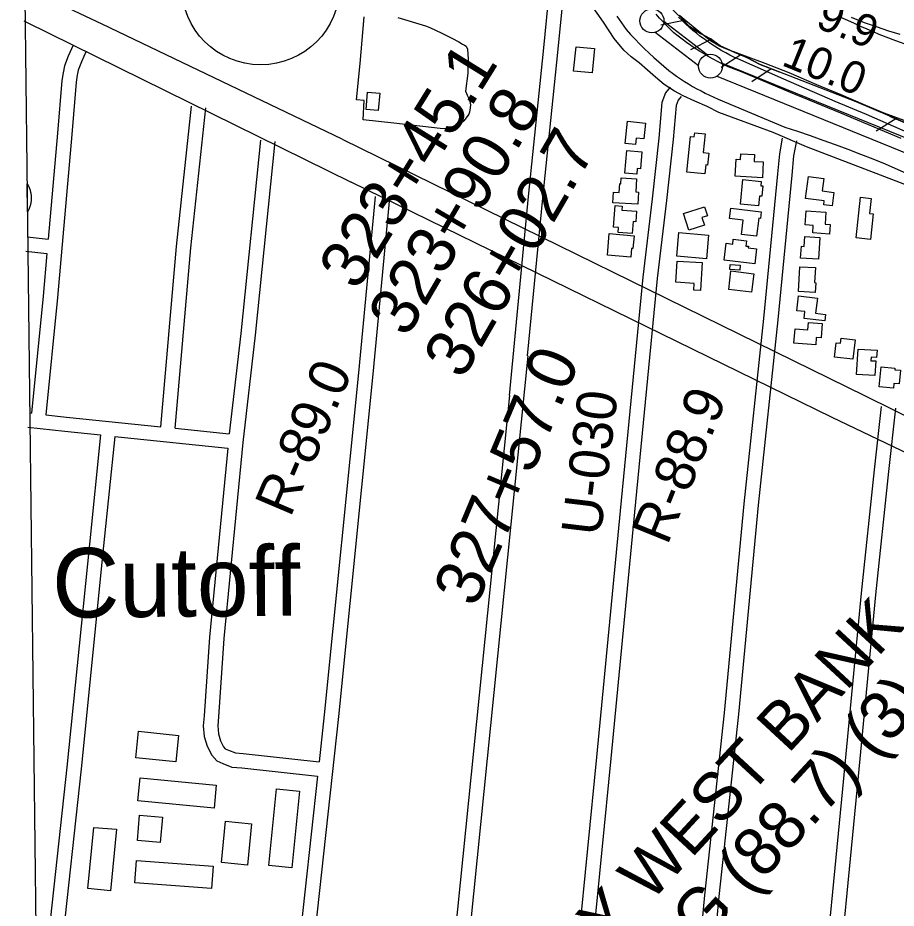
# Model space of a CAD drawing. Extents: x 3704301 to 3742427, y 506229 to 532009.
# Drawn here: x 3708455 to 3710287, y 518201 to 520058 of the extents above; entities that cross this region are included whole.
import ezdxf

# ---------------------------------------------------------------- set-up
doc = ezdxf.new("R2010")
doc.units = 0
for name, color, linetype in [('V-BLDG-OTLN', 7, 'Continuous'), ('V-CHAN-NAID', 7, 'Continuous'), ('V-DOMW-TANK', 7, 'Continuous'), ('V-FLOD-BASE', 7, 'Continuous'), ('V-GRID-FRAM', 7, 'Continuous'), ('V-LEVE-TOET', 7, 'Continuous'), ('V-RIVR-RANG', 7, 'Continuous'), ('V-RIVR-RANG-IDEN', 7, 'Continuous'), ('V-ROAD-CNTR', 7, 'Continuous'), ('V-ROAD-IDEN', 7, 'Continuous'), ('V-RRAP-FSHR', 7, 'Continuous'), ('V-SITE-OTLN', 7, 'Continuous'), ('V-SITE-VEGE', 7, 'Continuous'), ('V-SURV-IDEN', 7, 'Continuous'), ('V-SURV-LINE', 7, 'Continuous'), ('V-TOPO-GNAM-IDEN', 7, 'Continuous'), ('V-TOPO-SHOR', 7, 'Continuous')]:
    doc.layers.add(name, color=color, linetype=linetype)

msp = doc.modelspace()

# ---------------------------------------------------------------- linework, layer by layer
at = {"layer": 'V-BLDG-OTLN'}
for points in [[(3709657.9, 519994.1), (3709652.9, 519943.4), (3709614.4, 519947.3), (3709619.5, 519997.9)], [(3709210.2, 519901.3), (3709207.1, 519864.9), (3709181.6, 519867), (3709184.7, 519903.4)], [(3709743.8, 519793.8), (3709721.7, 519796.1), (3709726.5, 519842.5), (3709764.1, 519838.6), (3709760.7, 519805.7), (3709745.2, 519807.3)], [(3709888.3, 519732.5), (3709850.3, 519736.3), (3709857.9, 519810.7), (3709866.2, 519809.9), (3709867.1, 519818.6), (3709889, 519816.4), (3709885, 519777.3), (3709896.6, 519776.1), (3709894, 519751.1), (3709890.2, 519751.5)], [(3709721.4, 519734.4), (3709725.3, 519781.5), (3709756.6, 519778.9), (3709753.7, 519743.3), (3709746.9, 519743.9), (3709746, 519732.4)], [(3710008.1, 519724.4), (3709951.2, 519727.9), (3709953.3, 519763.2), (3709962.8, 519762.7), (3709963.5, 519774.6), (3709991.5, 519772.9), (3709990.7, 519758.8), (3710010.1, 519757.6)], [(3709744.1, 519695), (3709749.7, 519694.6), (3709748.3, 519669.6), (3709696.5, 519672.4), (3709697.8, 519694.5), (3709709.5, 519693.9), (3709710.5, 519712.4), (3709712.9, 519712.2), (3709713.5, 519724.4), (3709745.6, 519722.6)], [(3710000.3, 519665.9), (3709962.4, 519669.5), (3709967.2, 519720.7), (3710005.7, 519717.1), (3710004.8, 519708), (3710009, 519707.6), (3710007, 519686), (3710002.3, 519686.5)], [(3710098.4, 519681.6), (3710104.6, 519727.1), (3710136.5, 519722.7), (3710133, 519697.1), (3710157.5, 519693.8), (3710153.7, 519666), (3710136, 519668.4), (3710137, 519676.3)], [(3710233.8, 519596.1), (3710204.1, 519599.2), (3710213, 519683.9), (3710234.8, 519681.6), (3710231.5, 519650.3), (3710239.4, 519649.5)], [(3709738.7, 519633.3), (3709736.8, 519608.3), (3709707.2, 519610.6), (3709708, 519620.8), (3709697.4, 519621.6), (3709700.8, 519666.4), (3709715.9, 519665.2), (3709715.3, 519657.3), (3709745.6, 519654.9), (3709743.9, 519632.9)], [(3709843.8, 519650.1), (3709887.7, 519663.7), (3709893.4, 519645.1), (3709882.1, 519641.6), (3709887.1, 519625.4), (3709854.6, 519615.3)], [(3709968, 519636.2), (3709939.9, 519639.7), (3709942.6, 519661.1), (3710005.9, 519653.2), (3710004.2, 519639.7), (3710000.6, 519640.1), (3709995.9, 519602.6), (3709964.3, 519606.5)], [(3710099.6, 519655.9), (3710140.7, 519652.8), (3710138.9, 519627.7), (3710149.4, 519626.9), (3710148, 519607.2), (3710113.3, 519609.8), (3710114.4, 519625.3), (3710097.4, 519626.5)], [(3709735.2, 519577.1), (3709733.7, 519558.9), (3709685, 519563), (3709688.8, 519608.1), (3709740.5, 519603.7), (3709738.2, 519576.9)], [(3709891.5, 519555.7), (3709829.8, 519560.7), (3709833.8, 519610.1), (3709895.5, 519605.1)], [(3710128.2, 519599.6), (3710125.1, 519554.5), (3710088, 519557), (3710089.7, 519581.8), (3710095.2, 519581.5), (3710096.6, 519601.8)], [(3709996.2, 519576.1), (3709992.7, 519545.3), (3709928.3, 519552.6), (3709932.3, 519587.8), (3709946.3, 519586.3), (3709947.4, 519596.3), (3709975.1, 519593.1), (3709973.9, 519582.2), (3709979.1, 519581.6), (3709978.7, 519578.1)], [(3709827.5, 519506.5), (3709830.2, 519550.8), (3709882.9, 519547.7), (3709879.4, 519489.5), (3709865.3, 519490.4), (3709866.1, 519504.2)], [(3709961.1, 519531.8), (3709940.2, 519533.3), (3709940.9, 519543.8), (3709961.9, 519542.3)], [(3709937.9, 519491.4), (3709942.6, 519530.2), (3709990.3, 519524.4), (3709985.7, 519485.7)], [(3710083.7, 519487.1), (3710086.4, 519539), (3710118.8, 519537.3), (3710117.1, 519505.9), (3710119.6, 519505.7), (3710118.6, 519485.3)], [(3710096.9, 519445.2), (3710079.9, 519447.1), (3710083.4, 519478.1), (3710122.8, 519473.6), (3710119.2, 519442), (3710139.8, 519439.6), (3710138.2, 519426.2), (3710095.3, 519431.1)], [(3710103.3, 519407.2), (3710104.5, 519422.7), (3710133.2, 519420.5), (3710130.9, 519390.3), (3710120.5, 519391), (3710119.4, 519376), (3710074.1, 519379.4), (3710076.4, 519409.2)], [(3710171.4, 519379.3), (3710172.6, 519389.6), (3710201.4, 519386.3), (3710196.8, 519346), (3710158.6, 519350.3), (3710162, 519380.4)], [(3710244.7, 519342.3), (3710242.8, 519311.8), (3710204.3, 519314.2), (3710207.6, 519367.3), (3710247.4, 519364.8), (3710246.5, 519349.7), (3710235, 519350.4), (3710234.5, 519342.9)], [(3710251.6, 519288.5), (3710255.9, 519330), (3710284.7, 519327.1), (3710284.3, 519324), (3710296.3, 519322.8), (3710293.4, 519294.3), (3710282.5, 519295.4), (3710281.5, 519285.4)], [(3708784.9, 518505.8), (3708701.6, 518514.3), (3708707.2, 518569.8), (3708790.6, 518561.2)], [(3708864.5, 518409.2), (3708705.7, 518424.3), (3708710.3, 518472.3), (3708869, 518457.2)], [(3708978.6, 518289.6), (3708994.5, 518449.6), (3709042.6, 518444.8), (3709026.7, 518284.9)], [(3708757, 518390.3), (3708752.4, 518337.9), (3708704.5, 518342.1), (3708709.1, 518394.5)], [(3708880.2, 518295.8), (3708888.7, 518381.9), (3708942.9, 518376.5), (3708934.4, 518290.4)], [(3708613.4, 518368.8), (3708661.1, 518365.4), (3708648.5, 518236.8), (3708601, 518241.5)], [(3708862.4, 518288.2), (3708858.9, 518241.9), (3708699.4, 518253.8), (3708702.9, 518300.1)]]:
    msp.add_lwpolyline(points, close=True, dxfattribs=at)
at = {"layer": 'V-DOMW-TANK'}
for p, q in [((3708475.6, 519653.4), (3708474.9, 519712.2)), ((3708474.9, 519712.2), (3708474.9, 519712.2)), ((3708474.9, 519712.2), (3708475.4, 519711.3)), ((3708475.4, 519711.3), (3708475.9, 519710.4)), ((3708475.9, 519710.4), (3708476.4, 519709.5)), ((3708476.4, 519709.5), (3708476.9, 519708.6)), ((3708476.9, 519708.6), (3708477.3, 519707.7)), ((3708477.3, 519707.7), (3708477.8, 519706.7)), ((3708477.8, 519706.7), (3708478.2, 519705.8)), ((3708478.2, 519705.8), (3708478.6, 519704.9)), ((3708478.6, 519704.9), (3708479, 519703.9)), ((3708479, 519703.9), (3708479.4, 519703)), ((3708479.4, 519703), (3708479.7, 519702)), ((3708479.7, 519702), (3708480.1, 519701)), ((3708480.1, 519701), (3708480.4, 519700.1)), ((3708480.4, 519700.1), (3708480.7, 519699.1)), ((3708480.7, 519699.1), (3708481, 519698.1)), ((3708481, 519698.1), (3708481.2, 519697.1)), ((3708481.2, 519697.1), (3708481.5, 519696.1)), ((3708481.5, 519696.1), (3708481.7, 519695.1)), ((3708481.7, 519695.1), (3708481.9, 519694.1)), ((3708481.9, 519694.1), (3708482.1, 519693.1)), ((3708482.1, 519693.1), (3708482.3, 519692.1)), ((3708482.3, 519692.1), (3708482.5, 519691.1)), ((3708482.6, 519673.8), (3708482.4, 519672.8)), ((3708482.5, 519691.1), (3708482.6, 519690.1)), ((3708482.6, 519690.1), (3708482.8, 519689.1)), ((3708482.7, 519674.8), (3708482.6, 519673.8)), ((3708482.8, 519675.8), (3708482.7, 519674.8)), ((3708482.8, 519689.1), (3708482.9, 519688.1)), ((3708482.9, 519676.9), (3708482.8, 519675.8)), ((3708482.9, 519688.1), (3708483, 519687.1)), ((3708483, 519677.9), (3708482.9, 519676.9)), ((3708483, 519687.1), (3708483, 519686)), ((3708483, 519686), (3708483.1, 519685)), ((3708483.1, 519678.9), (3708483, 519677.9)), ((3708483.1, 519685), (3708483.1, 519684)), ((3708483.1, 519684), (3708483.2, 519683)), ((3708483.2, 519682), (3708483.1, 519680.9)), ((3708483.1, 519680.9), (3708483.1, 519679.9)), ((3708483.1, 519679.9), (3708483.1, 519678.9)), ((3708483.2, 519683), (3708483.2, 519682)), ((3708476.7, 519655.4), (3708476.2, 519654.5)), ((3708477.1, 519656.3), (3708476.7, 519655.4)), ((3708477.6, 519657.2), (3708477.1, 519656.3)), ((3708478, 519658.2), (3708477.6, 519657.2)), ((3708478.4, 519659.1), (3708478, 519658.2)), ((3708478.8, 519660), (3708478.4, 519659.1)), ((3708479.2, 519661), (3708478.8, 519660)), ((3708479.5, 519661.9), (3708479.2, 519661)), ((3708479.9, 519662.9), (3708479.5, 519661.9)), ((3708480.2, 519663.9), (3708479.9, 519662.9)), ((3708480.5, 519664.8), (3708480.2, 519663.9)), ((3708480.8, 519665.8), (3708480.5, 519664.8)), ((3708481.1, 519666.8), (3708480.8, 519665.8)), ((3708481.4, 519667.8), (3708481.1, 519666.8)), ((3708481.6, 519668.8), (3708481.4, 519667.8)), ((3708481.8, 519669.8), (3708481.6, 519668.8)), ((3708482, 519670.8), (3708481.8, 519669.8)), ((3708482.2, 519671.8), (3708482, 519670.8)), ((3708482.4, 519672.8), (3708482.2, 519671.8)), ((3708475.7, 519653.6), (3708475.6, 519653.4)), ((3708476.2, 519654.5), (3708475.7, 519653.6))]:
    msp.add_line(p, q, dxfattribs=at)
at = {"layer": 'V-FLOD-BASE'}
msp.add_lwpolyline([(3710297.4, 519806.7), (3710172, 519859.3), (3710066.5, 519902.6), (3709964.3, 519945.8), (3709936.8, 519956.1), (3709925.5, 519961.8), (3709915.6, 519966.7), (3709905.8, 519971.9), (3709896.2, 519977.2), (3709886.7, 519982.8), (3709877.3, 519988.6), (3709868, 519994.5), (3709858.9, 520000.7), (3709849.9, 520007), (3709841, 520013.6), (3709832.3, 520020.3), (3709823.7, 520027.2), (3709815.9, 520034.6), (3709808.3, 520042.2), (3709800.9, 520049.9), (3709793.6, 520057.8), (3709786.4, 520065.8)], dxfattribs=at)
at = {"layer": 'V-GRID-FRAM'}
msp.add_lwpolyline([(3708355.7, 529827.8), (3740022.4, 530214.7), (3740252.5, 512033.3), (3708569.9, 511646.2), (3708355.7, 529827.8)], dxfattribs=at)
at = {"layer": 'V-LEVE-TOET'}
for points in [[(3709704.5, 520061.8), (3709724, 520033.8), (3709733.2, 520023.7), (3709742.6, 520013.7), (3709752.2, 520003.9), (3709761.9, 519994.2), (3709771.9, 519984.7), (3709781.9, 519975.4), (3709792.1, 519966.3), (3709802.5, 519957.3), (3709813, 519948.5), (3709821, 519942.5), (3709829.1, 519936.7), (3709837.3, 519931.1), (3709845.7, 519925.6), (3709854.1, 519920.4), (3709862.7, 519915.3), (3709871.4, 519910.4), (3709880.2, 519905.7), (3709889, 519901.1), (3709898, 519896.8), (3709907.1, 519892.7), (3709916.2, 519888.7), (3709950.7, 519873.8), (3709985.3, 519859.1), (3710020.1, 519844.6), (3710054.9, 519830.4), (3710081.4, 519821.6), (3710107.8, 519812.5), (3710134.1, 519803.3), (3710160.3, 519793.7), (3710186.5, 519784), (3710212.6, 519774), (3710238.6, 519763.8), (3710264.5, 519753.4), (3710309.7, 519733.3)], [(3709908.1, 519999.1), (3709900.3, 520004.2), (3709892.7, 520009.4), (3709885.2, 520014.8), (3709877.8, 520020.3), (3709870.5, 520026), (3709863.3, 520031.9), (3709856.3, 520037.9), (3709848.5, 520045.1), (3709840.9, 520052.4), (3709833.4, 520059.9)], [(3710356.5, 519799), (3710225.4, 519856.4), (3710160.2, 519883.6), (3710053.2, 519930.2), (3709956.7, 519972.5), (3709948.3, 519976.5), (3709940.1, 519980.6), (3709931.9, 519985), (3709923.9, 519989.5), (3709915.9, 519994.2), (3709908.1, 519999.1)]]:
    msp.add_lwpolyline(points, dxfattribs=at)
at = {"layer": 'V-ROAD-CNTR'}
for points in [[(3709591, 520166.5), (3709579.2, 520155.1), (3709569.3, 520146.5), (3709564.1, 520124.2), (3709550.8, 519988.8), (3709519.5, 519685.2), (3709479.8, 519270.1)], [(3709611.8, 520144.8), (3709599.4, 520133), (3709596.3, 520130.3), (3709593.7, 520119.3), (3709580.7, 519985.8), (3709549.4, 519682.2), (3709517.9, 519353.1)], [(3709131.7, 519805), (3708630.8, 520045.2), (3708467, 520122.6)], [(3710319.9, 519704.9), (3710100.2, 519789), (3710030.6, 519818.7), (3709917.5, 519860.7), (3709892.7, 519873.5), (3709867.5, 519884.3), (3709843.2, 519895.3), (3709825.2, 519905.2), (3709803.6, 519919.2), (3709784.9, 519934.4), (3709768.7, 519949.4), (3709751.3, 519964.2), (3709734.8, 519977.2), (3709718.9, 519990.9), (3709699, 520014.9), (3709676.5, 520048.9), (3709620.7, 520129.6)], [(3708467.8, 520052.1), (3708472.2, 520050), (3709150.8, 519715.7)], [(3708570.6, 520000.9), (3708560.4, 519978.1), (3708552.4, 519957.8), (3708549.5, 519943.4), (3708547.2, 519927.4), (3708538.2, 519817.7), (3708518.5, 519596.6)], [(3708598, 519988.6), (3708588.1, 519966.5), (3708581.3, 519949.2), (3708579, 519938.3), (3708577, 519924.1), (3708568.1, 519815.1), (3708537.7, 519474.5), (3708513.4, 519230.1)], [(3709815.9, 519913.7), (3709805.8, 519901.7), (3709798.6, 519881.8), (3709792.1, 519807.5), (3709778.3, 519680.9), (3709758.6, 519517.4), (3709711.5, 519029.5), (3709661.9, 518516), (3709606.1, 517943.7)], [(3709838.8, 519894.4), (3709832.2, 519886.5), (3709828.1, 519875.3), (3709822, 519804.6), (3709808.1, 519677.4), (3709788.4, 519514.1), (3709741.4, 519026.6), (3709691.8, 518513.1), (3709636, 517941.2)], [(3708753.5, 519204.9), (3708786.3, 519581.4), (3708817.7, 519874)], [(3708783.4, 519201.8), (3708816.2, 519578.5), (3708847.6, 519870.8)], [(3709131.7, 519805), (3710222.7, 519269.3), (3710510, 519127.5)], [(3710049.7, 519807), (3710043.6, 519774.6), (3710040, 519732.6), (3710010.3, 519431.1), (3709969.6, 519044.2), (3709928.4, 518608.3), (3709887.2, 518227.9), (3709858.9, 517922.7)], [(3708991, 519800.2), (3708950.2, 519396.1), (3708924.5, 519172), (3708884.8, 518763.4), (3708873.6, 518599.7), (3708872.2, 518581.4), (3708873.6, 518564.4), (3708877.8, 518549.7), (3708884.4, 518537.1), (3708887.8, 518533.3), (3708894.7, 518530.3), (3708908.9, 518524.5), (3708924.9, 518523.2), (3709083.5, 518505.9)], [(3708961.2, 519803.3), (3708920.4, 519399.3), (3708896.3, 519190)], [(3710079.1, 519801.5), (3710073.3, 519770.5), (3710069.9, 519729.9), (3710040.2, 519428.1), (3709999.5, 519041.2), (3709958.3, 518605.3), (3709917.1, 518224.9), (3709888.8, 517920.2)], [(3710505.3, 519055.9), (3710153.4, 519224.7), (3709150.8, 519715.7)], [(3709230.2, 519682.7), (3709195.9, 519314.9), (3709124.1, 518600.9), (3709057.2, 517989.4)], [(3709200.3, 519685.5), (3709166.1, 519317.8), (3709094.3, 518604), (3709083.5, 518505.9)], [(3708474.9, 519601.4), (3708518.5, 519596.6)], [(3708471.7, 519571.5), (3708515.8, 519566.7)], [(3708515.8, 519566.7), (3708507.8, 519477.3), (3708483.6, 519233.4)], [(3709519.2, 519353), (3709384.9, 518023.7), (3709378.8, 517962.6)], [(3709480.7, 519270), (3709355, 518026.7), (3709348.9, 517965.1)], [(3710255.7, 519247.3), (3710241, 519114.9), (3710214.3, 518857.6), (3710175.4, 518449.8), (3710128.7, 517969.6), (3710122.1, 517900.8)], [(3708479.3, 519233.8), (3708483.6, 519233.4)], [(3708513.4, 519230.1), (3708556.6, 519225.4), (3708753.5, 519204.9)], [(3710285.6, 519244), (3710270.9, 519111.7), (3710244.1, 518854.6), (3710205.3, 518446.9), (3710158.6, 517966.7), (3710152, 517898.3)], [(3708476, 519204), (3708553.4, 519195.6), (3708627.7, 519187.9)], [(3708783.4, 519201.8), (3708896.3, 519190)], [(3708627.7, 519187.9), (3708604.4, 518960), (3708557.7, 518494.8), (3708516.1, 518117.1), (3708509.2, 518028)], [(3708657.5, 519184.8), (3708634.2, 518956.9), (3708587.6, 518491.7), (3708546, 518114.3), (3708539.1, 518025.9)], [(3708657.5, 519184.8), (3708892.9, 519160.2)], [(3708893.2, 519160.2), (3708854.9, 518765.9), (3708843.6, 518601.8), (3708842.1, 518581.3), (3708843.9, 518559.1), (3708849.8, 518538.5), (3708859.7, 518519.7), (3708870, 518508.4), (3708882.9, 518502.7), (3708901.8, 518494.9), (3708922.1, 518493.3), (3709080.3, 518476.1)], [(3709080.3, 518476.1), (3709027.3, 517991.9)]]:
    msp.add_lwpolyline(points, dxfattribs=at)
at = {"layer": 'V-ROAD-IDEN'}
msp.add_circle((3708961.7, 520125.1), 165, dxfattribs=at)
at = {"layer": 'V-RRAP-FSHR'}
for p, q in [((3709844.2, 520052.5), (3709796.3, 520043.3)), ((3709901.9, 520013.7), (3709858.3, 519991.7)), ((3709963.2, 519981), (3709922.1, 519954.8)), ((3710026.8, 519951.9), (3709986.1, 519924.8)), ((3710286.6, 519847.7), (3710245.2, 519821.8))]:
    msp.add_line(p, q, dxfattribs=at)
for points in [[(3709670.9, 520290.7), (3709674.8, 520287.2), (3709693, 520271.6), (3709703.8, 520259.4), (3709712.5, 520251.5), (3709720.6, 520236.6), (3709750.2, 520176.6), (3709765.1, 520152), (3709780.4, 520131.3), (3709795.9, 520107.8), (3709807.8, 520090.6), (3709824.7, 520071.4), (3709841.4, 520055.3), (3709856.9, 520039.8), (3709879.3, 520025.8), (3709900.1, 520014.7), (3709920.1, 519999.5), (3709949.6, 519986.7), (3709975.7, 519975.8), (3710003.3, 519961), (3710043, 519945.5)], [(3711169.9, 519494.4), (3710970.9, 519572), (3710948, 519585.8), (3710932.2, 519597.2), (3710903.7, 519610.2), (3710868.7, 519615.5), (3710834, 519626), (3710760.1, 519647.1), (3710540.5, 519740), (3710203.8, 519882.8), (3710003.3, 519961), (3709975.7, 519975.8), (3709949.6, 519986.7), (3709920.1, 519999.5), (3709900.1, 520014.7), (3709879.3, 520025.8), (3709856.9, 520039.8), (3709841.4, 520055.3), (3709824.7, 520071.4)], [(3710273.5, 519853.3), (3710540.5, 519740), (3710760.1, 519647.1), (3710834, 519626), (3710852.4, 519620.5)]]:
    msp.add_lwpolyline(points, dxfattribs=at)
at = {"layer": 'V-SITE-OTLN'}
msp.add_lwpolyline([(3709247.6, 520058.9), (3709305.8, 520041.6), (3709314.8, 520037.8), (3709339.4, 520026.1), (3709360.7, 520015.7), (3709375.3, 520008.2), (3709382.9, 520003.5), (3709386.7, 520001.1), (3709390, 519998.8), (3709393.3, 519993.1), (3709394.8, 519971.9), (3709393.5, 519943), (3709388.8, 519905.2), (3709390.7, 519900.5), (3709392.6, 519897.2), (3709395.5, 519891.5), (3709397.9, 519883.5), (3709399.3, 519876.9), (3709398.8, 519870.2), (3709397.4, 519861.7), (3709395.6, 519857), (3709390.4, 519849.4), (3709385.7, 519843.7), (3709379.5, 519838), (3709373.9, 519833.8), (3709369.2, 519829), (3709366.3, 519826.7), (3709363.5, 519825.2), (3709359.7, 519825.7), (3709336.1, 519827.5), (3709239.6, 519838.7), (3709175.8, 519845.6), (3709177.6, 519885.8), (3709161.5, 519887.2), (3709168.9, 519962.8), (3709177.6, 520060.2)], dxfattribs=at)
at = {"layer": 'V-SITE-VEGE'}
msp.add_lwpolyline([(3710295.8, 520023.5), (3710272, 520030.5), (3710246.5, 520039.4), (3710220.9, 520047.7), (3710194.1, 520058.9)], dxfattribs=at)
at = {"layer": 'V-SURV-LINE'}
for points in [[(3709802.8, 520051.6), (3709893.3, 519981.7)], [(3709875, 519958), (3709784.5, 520027.8)], [(3709924.1, 519964), (3711342.4, 519387.4)], [(3711331.1, 519359.6), (3709912.8, 519936.2)]]:
    msp.add_lwpolyline(points, dxfattribs=at)
for centre in [(3709777.8, 520051.9), (3709899.9, 519957.6)]:
    msp.add_circle(centre, 25, dxfattribs=at)
at = {"layer": 'V-TOPO-SHOR'}
for points in [[(3710360.9, 519822.9), (3710262, 519859.5), (3710224.1, 519875), (3710172.6, 519897.6), (3710121.9, 519918.8), (3710063.7, 519943.2), (3710014.1, 519962.9), (3709972.9, 519978.4), (3709935.5, 519992.1), (3709918.5, 519999.1), (3709900, 520010.4), (3709883.4, 520023.6), (3709867.8, 520035.8), (3709856, 520045.7), (3709845.1, 520054.7), (3709835.6, 520063.2)], [(3710171.2, 520059.3), (3710185.4, 520053.6), (3710199.6, 520047), (3710211, 520041.9), (3710226.1, 520035.3), (3710239.4, 520029.6), (3710251.2, 520024.5), (3710285.7, 520011.3), (3710312.7, 520001.5)]]:
    msp.add_lwpolyline(points, dxfattribs=at)

# ---------------------------------------------------------------- texts
at = {"layer": 'V-CHAN-NAID'}
for s, p in [('CHLAMETTE FERRY WEST BANK', (3708865.8, 517228.5)), ('MAINTENANCE LANDING (88.7) (3)', (3708864.1, 517020.5))]:
    msp.add_text(s, height=100, rotation=47.2274, dxfattribs=at).set_placement(p)
at = {"layer": 'V-RIVR-RANG'}
for s, p in [('9.9', (3710116.6, 520039.4)), ('9.9', (3710116.6, 520039.4)), ('10.0', (3710045.8, 519960.3)), ('10.0', (3710045.8, 519960.3))]:
    msp.add_text(s, height=67, rotation=337.8183, dxfattribs=at).set_placement(p)
at = {"layer": 'V-RIVR-RANG-IDEN'}
for s, rotation, p in [('R-89.0', 66.9583, (3709023.6, 519014)), ('R-88.9', 67.9622, (3709810, 518956)), ('U-030', 83.1273, (3709670.8, 518975.3))]:
    msp.add_text(s, height=83, rotation=rotation, dxfattribs=at).set_placement(p)
at = {"layer": 'V-SURV-IDEN'}
for s, rotation, p in [('323+45.1', 58.163, (3709162.3, 519486.5)), ('323+90.8', 59.6516, (3709266.8, 519388.7)), ('326+02.7', 59.9312, (3709382.7, 519301.1)), ('327+57.0', 67.1972, (3709410.9, 518825.6))]:
    msp.add_text(s, height=100, rotation=rotation, dxfattribs=at).set_placement(p)
at = {"layer": 'V-TOPO-GNAM-IDEN'}
msp.add_text('Cutoff', height=145, rotation=0.4872, dxfattribs=at).set_placement((3708527.4, 518806.6))

doc.saveas('drawing.dxf')
